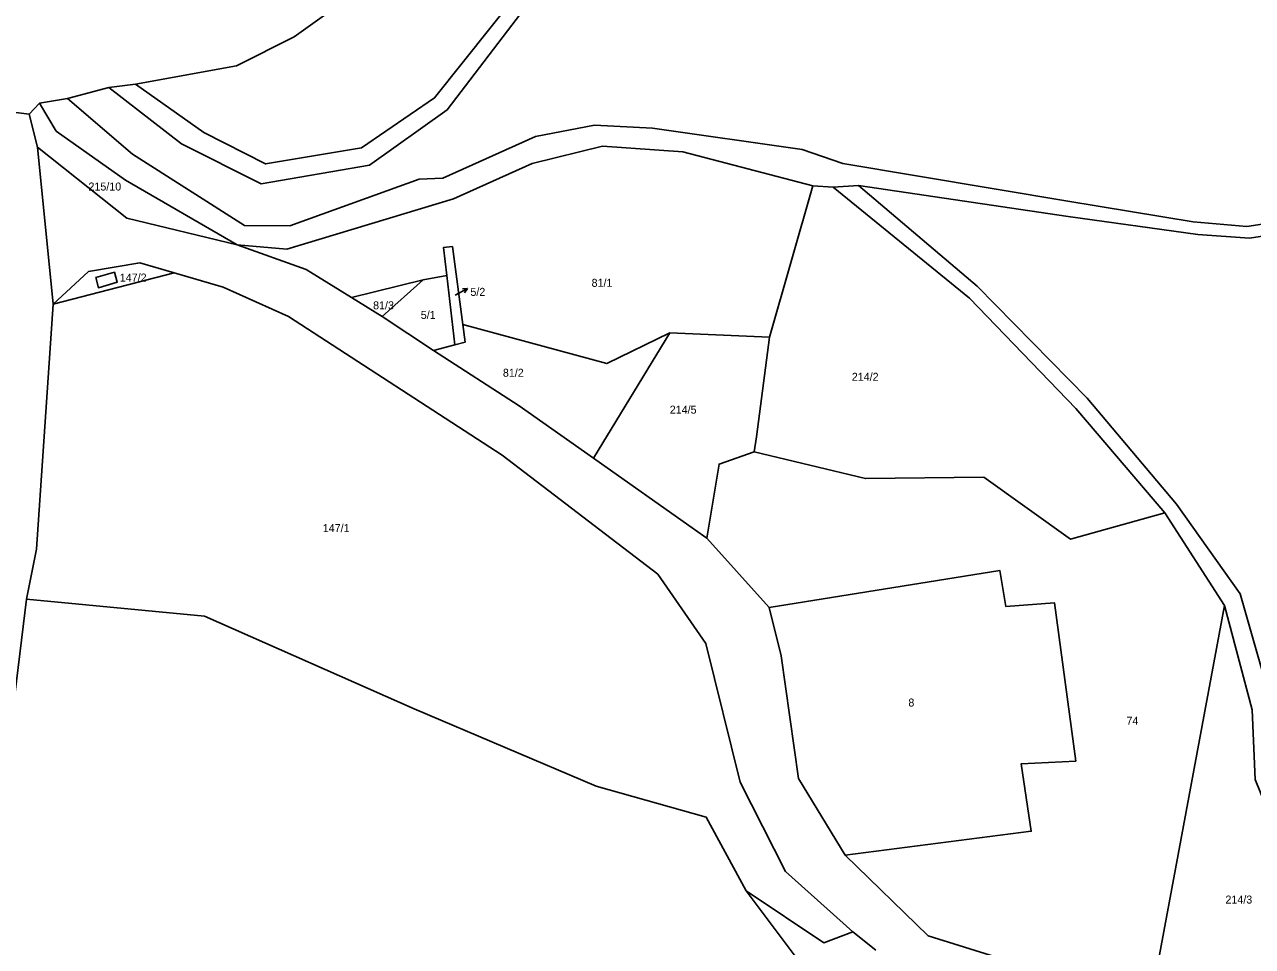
# Model space of a CAD drawing. Extents: x -880531 to -877616, y -1023932 to -1021350.
# Drawn here: x -878781.4 to -878520.6, y -1022705.7 to -1022509.8 of the extents above; entities that cross this region are included whole.
import ezdxf

# ---------------------------------------------------------------- set-up
doc = ezdxf.new("R2010")
doc.units = 0
for name, color, linetype in [('Hranice parcel', 7, 'Continuous'), ('Parcelní čísla', 7, 'Continuous'), ('Pop  PČ popisy', 7, 'Continuous'), ('Vnitřní kresba', 7, 'Continuous')]:
    doc.layers.add(name, color=color, linetype=linetype)

msp = doc.modelspace()

# ---------------------------------------------------------------- linework, layer by layer
at = {"layer": 'Hranice parcel'}
for p, q in [((-878763.51, -1022523.14), (-878772.34, -1022525.45)), ((-878757.9, -1022522.41), (-878763.51, -1022523.14)), ((-878772.34, -1022525.45), (-878778.26, -1022526.5)), ((-878780.45, -1022528.79), (-878790.48, -1022527.57)), ((-878778.26, -1022526.5), (-878780.45, -1022528.79)), ((-878780.45, -1022528.79), (-878778.69, -1022535.8)), ((-878775.4, -1022569.16), (-878778.69, -1022535.8)), ((-878613.98, -1022544.07), (-878623.18, -1022576.23)), ((-878609.63, -1022544.29), (-878613.98, -1022544.07)), ((-878604.26, -1022543.95), (-878609.63, -1022544.29)), ((-878690.52, -1022556.95), (-878688.34, -1022573.54)), ((-878749.64, -1022562.54), (-878775.4, -1022569.16)), ((-878711.97, -1022567.78), (-878696.77, -1022564)), ((-878696.77, -1022564), (-878705.46, -1022571.8)), ((-878696.77, -1022564), (-878691.74, -1022563.07)), ((-878690.04, -1022577.86), (-878691.74, -1022563.07)), ((-878705.46, -1022571.8), (-878711.97, -1022567.78)), ((-878694.59, -1022579.04), (-878705.46, -1022571.8)), ((-878660.58, -1022601.91), (-878644.32, -1022575.31)), ((-878644.32, -1022575.31), (-878623.18, -1022576.23)), ((-878690.04, -1022577.86), (-878694.59, -1022579.04)), ((-878526.53, -1022633.22), (-878539.2, -1022613.53)), ((-878636.49, -1022618.9), (-878623.22, -1022633.64)), ((-878541.54, -1022714.07), (-878526.53, -1022633.22)), ((-878600.6, -1022706.46), (-878605.47, -1022702.56))]:
    msp.add_line(p, q, dxfattribs=at)
for points in [[(-878108.11, -1022440.58), (-878152.15, -1022446.77), (-878167.86, -1022449.63), (-878217.16, -1022451.24), (-878301.33, -1022453.9), (-878333.67, -1022456.67), (-878366.21, -1022467.52), (-878407.13, -1022480.7), (-878435.64, -1022482.95), (-878455.12, -1022478.73), (-878537.04, -1022450.63), (-878561.34, -1022444.97), (-878578.99, -1022444.28), (-878605.69, -1022449.33), (-878637.81, -1022454.4), (-878653.86, -1022459.64), (-878669.06, -1022467.56), (-878706.56, -1022499.73), (-878724.15, -1022512.39), (-878736.44, -1022518.55), (-878757.9, -1022522.41)], [(-878757.9, -1022522.41), (-878743.38, -1022532.72), (-878730.23, -1022539.4), (-878709.85, -1022535.98), (-878694.32, -1022525.35), (-878670.27, -1022495.13), (-878649.48, -1022475.44), (-878635.27, -1022470.68), (-878614.41, -1022478.04), (-878543.73, -1022482.35), (-878506.92, -1022500.7), (-878475.11, -1022508.02), (-878399.08, -1022508.59), (-878373.94, -1022502.74), (-878346.19, -1022490.2), (-878334.94, -1022490.41), (-878279.22, -1022499.74), (-878220.51, -1022507.42), (-878194.43, -1022507.39), (-878145.84, -1022503.8), (-878124.82, -1022500.78)], [(-878125.35, -1022504.99), (-878146.35, -1022507.21), (-878194.02, -1022510.96), (-878220.76, -1022511.05), (-878280.27, -1022503.97), (-878335.4, -1022493.58), (-878344.86, -1022493.55), (-878371.73, -1022505.4), (-878399.1, -1022512.43), (-878475.7, -1022511.16), (-878508.77, -1022503.35), (-878545.47, -1022484.68), (-878615.6, -1022481.24), (-878635.5, -1022474.3), (-878648.14, -1022478.45), (-878668.08, -1022496.96), (-878691.68, -1022527.88), (-878708.19, -1022539.68), (-878731.2, -1022543.61), (-878748.07, -1022535.1), (-878763.51, -1022523.14)], [(-878772.34, -1022525.45), (-878758.55, -1022537.32), (-878734.74, -1022552.47), (-878725.11, -1022552.52), (-878697.59, -1022542.6), (-878692.56, -1022542.42), (-878672.91, -1022533.58), (-878660.33, -1022531.18), (-878648.04, -1022531.76), (-878616.24, -1022536.33), (-878607.61, -1022539.29), (-878559.76, -1022547.29), (-878533.18, -1022551.67), (-878521.77, -1022552.65), (-878440.9, -1022540.29), (-878419.64, -1022538.34), (-878389.99, -1022539.7), (-878317.85, -1022548.39), (-878303.92, -1022544.55), (-878256.37, -1022525.75), (-878245.48, -1022524.13), (-878233.68, -1022525.33), (-878151.01, -1022540.9)], [(-878736.27, -1022556.57), (-878760.01, -1022542.82), (-878774.71, -1022532.4), (-878778.26, -1022526.5)], [(-878262.91, -1022531.2), (-878303.25, -1022547.39), (-878317.9, -1022551.31), (-878389.14, -1022542.46), (-878419.52, -1022540.9), (-878441.69, -1022542.71), (-878521.19, -1022555.14), (-878532.17, -1022554.36), (-878559.74, -1022550.55), (-878604.26, -1022543.95)], [(-878778.69, -1022535.8), (-878759.73, -1022550.92), (-878736.27, -1022556.57)], [(-878736.27, -1022556.57), (-878725.72, -1022557.5), (-878690.3, -1022546.83), (-878673.59, -1022539.3), (-878658.65, -1022535.64), (-878641.6, -1022536.84), (-878613.98, -1022544.07)], [(-878539.2, -1022613.53), (-878558.1, -1022591.32), (-878580.66, -1022567.89), (-878609.63, -1022544.29)], [(-878604.26, -1022543.95), (-878579.05, -1022565.36), (-878555.67, -1022589.18), (-878536.69, -1022611.71), (-878523.17, -1022630.71), (-878516.35, -1022654.55), (-878515.73, -1022669.9), (-878511.39, -1022678.27), (-878502.03, -1022685.87), (-878490.91, -1022688.03), (-878436.73, -1022684.88), (-878425.48, -1022682.64), (-878366.49, -1022657.36), (-878316.24, -1022643.18), (-878298.99, -1022642.4)], [(-878711.97, -1022567.78), (-878721.65, -1022561.8), (-878736.27, -1022556.57)], [(-878691.74, -1022563.07), (-878692.42, -1022557.14), (-878690.52, -1022556.95)], [(-878775.4, -1022569.16), (-878767.83, -1022562.27), (-878756.95, -1022560.39), (-878749.64, -1022562.54)], [(-878749.64, -1022562.54), (-878739.28, -1022565.58), (-878725.4, -1022571.84), (-878679.96, -1022601.24), (-878646.91, -1022626.55), (-878636.68, -1022641.3), (-878629.43, -1022670.74), (-878619.78, -1022689.73), (-878605.47, -1022702.56)], [(-878781.06, -1022631.86), (-878778.91, -1022621.22), (-878775.4, -1022569.16)], [(-878688.34, -1022573.54), (-878687.85, -1022577.29), (-878690.04, -1022577.86)], [(-878688.34, -1022573.54), (-878657.73, -1022581.8), (-878644.32, -1022575.31)], [(-878623.18, -1022576.23), (-878625.97, -1022597.36), (-878626.4, -1022600.58)], [(-878660.58, -1022601.91), (-878676.34, -1022590.8), (-878694.59, -1022579.04)], [(-878626.4, -1022600.58), (-878633.88, -1022603.17), (-878636.49, -1022618.9)], [(-878539.2, -1022613.53), (-878559.25, -1022619.14), (-878577.61, -1022605.93), (-878602.79, -1022606.25), (-878626.4, -1022600.58)], [(-878636.49, -1022618.9), (-878639.1, -1022617.06), (-878660.58, -1022601.91)], [(-878607.12, -1022686.24), (-878567.55, -1022681.2), (-878569.7, -1022666.85), (-878558.09, -1022666.26), (-878562.64, -1022632.64), (-878572.95, -1022633.43), (-878574.22, -1022625.79), (-878623.22, -1022633.64)], [(-878781.06, -1022631.86), (-878792.13, -1022722.46), (-878817.64, -1022818.57), (-878818.61, -1022822.28)], [(-878628.11, -1022693.81), (-878636.6, -1022678.16), (-878660.01, -1022671.61), (-878698.7, -1022655.14), (-878743.19, -1022635.5), (-878781.06, -1022631.86)], [(-878623.22, -1022633.64), (-878620.72, -1022643.88), (-878617.02, -1022669.95), (-878607.12, -1022686.24)], [(-878503.14, -1022689.72), (-878515.73, -1022680.66), (-878520.02, -1022670.17), (-878520.65, -1022655.38), (-878526.53, -1022633.22)], [(-878607.12, -1022686.24), (-878589.44, -1022703.39), (-878567.47, -1022710.29), (-878541.54, -1022714.07)], [(-878652.74, -1022853.75), (-878641.61, -1022812.8), (-878629.32, -1022760.4), (-878617.11, -1022708.59), (-878628.11, -1022693.81)], [(-878605.47, -1022702.56), (-878611.64, -1022704.86), (-878628.11, -1022693.81)]]:
    msp.add_lwpolyline(points, dxfattribs=at)
at = {"layer": 'Pop  PČ popisy'}
for p, q in [((-878689.98, -1022567.25), (-878687.306, -1022565.888)), ((-878687.306, -1022565.888), (-878688.426, -1022565.896)), ((-878687.306, -1022565.888), (-878687.971, -1022566.788))]:
    msp.add_line(p, q, dxfattribs=at)
at = {"layer": 'Vnitřní kresba'}
msp.add_lwpolyline([(-878766.32, -1022563.55), (-878762.37, -1022562.39), (-878761.75, -1022564.53), (-878765.74, -1022565.69), (-878766.32, -1022563.55)], dxfattribs=at)

# ---------------------------------------------------------------- texts
at = {"layer": 'Parcelní čísla'}
for s, p in [('215/10', (-878767.87, -1022545.04)), ('147/2', (-878761.217, -1022564.38)), ('81/1', (-878660.976, -1022565.5)), ('5/2', (-878686.72, -1022567.42)), ('81/3', (-878707.396, -1022570.28)), ('5/1', (-878697.268, -1022572.32)), ('81/2', (-878679.82, -1022584.61)), ('214/2', (-878605.69, -1022585.47)), ('214/5', (-878644.366, -1022592.45)), ('147/1', (-878718.093, -1022617.61)), ('8', (-878593.668, -1022654.68)), ('74', (-878547.34, -1022658.57)), ('214/3', (-878526.3, -1022696.55))]:
    msp.add_text(s, height=1.7, dxfattribs=at).set_placement(p)

doc.saveas('drawing.dxf')
